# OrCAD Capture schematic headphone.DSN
size A4; title: My Design1; rev: A; company: Parallel Systems Ltd; note: DOC2345798; note: First Floor, Dorna House.; note: 2 Guildford Road, West End
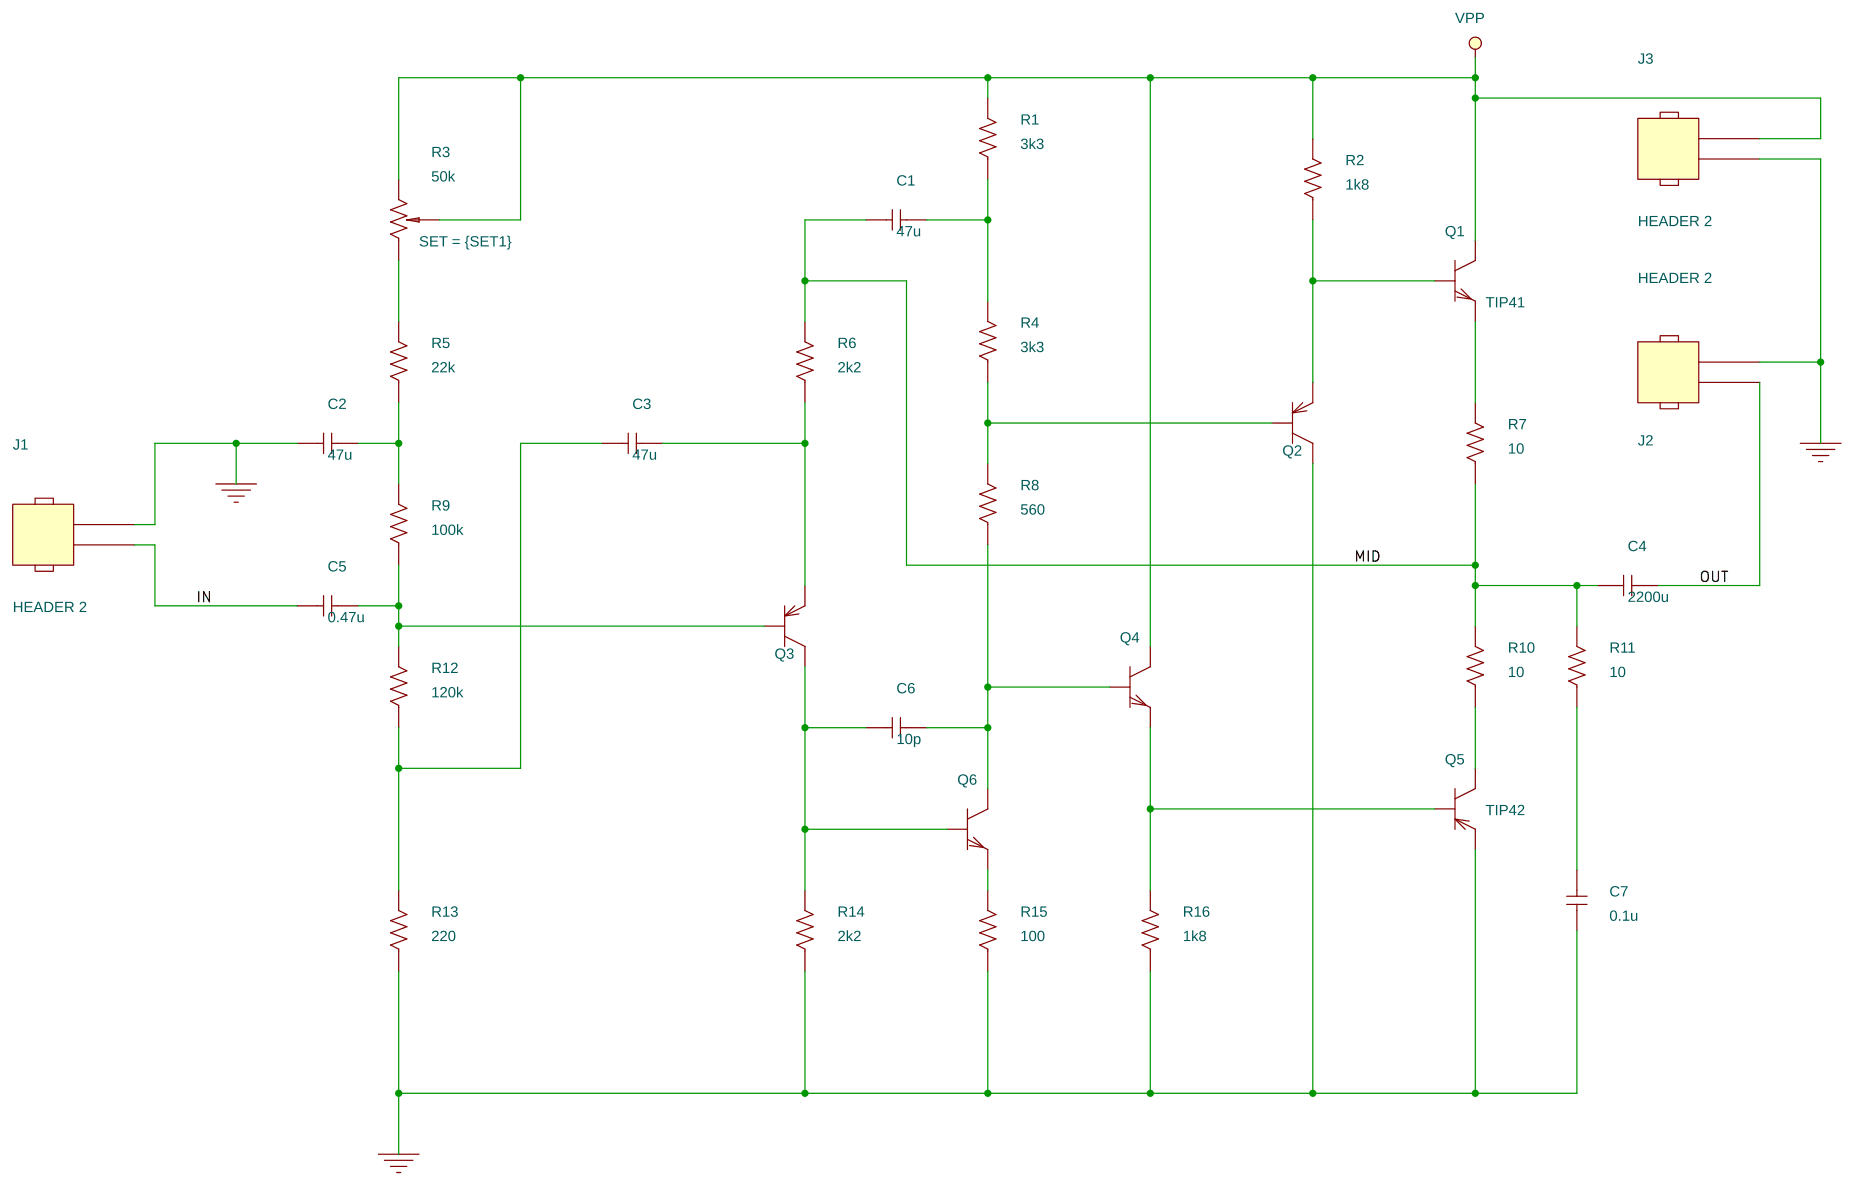
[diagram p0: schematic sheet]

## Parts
C1  47u  [smc0805]
C2  47u  [smc0805]
C3  47u  [smc0805]
C4  2200u  [smc1210]
C5  0.47u  [smc0805]
C6  10p  [smc0805]
C7  0.1u  [smc0805]
J1  HEADER 2  [jumper2]
J2  HEADER 2  [jumper2]
J3  HEADER 2  [jumper2]
Q1  TIP41  [to252aa]
Q2  BC212AP/ZTX  [to236ab]
Q3  BC212AP/ZTX  [to236ab]
Q4  BC182BP/ZTX  [to236ab]
Q5  TIP42  [to252aa]
Q6  BC182BP/ZTX  [to236ab]
R1  3k3  [smr0805]
R2  1k8  [smr0805]
R3  50k  [resadj]
R4  3k3  [smr0805]
R5  22k  [smr0805]
R6  2k2  [smr0805]
R7  10  [smr1206]
R8  560  [smr0805]
R9  100k  [smr0805]
R10  10  [smr0805]
R11  10  [smr0805]
R12  120k  [smr0805]
R13  220  [smr0805]
R14  2k2  [smr0805]
R15  100  [smr0805]
R16  1k8  [smr0805]

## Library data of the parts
C1-C7 = C
J1-J3 = HEADER_2
Q1 = TIP41
Q2 Q3 = BC212AP_ZTX_0
Q4 Q6 = BC182BP_ZTX_0
Q5 = TIP42
R1 R2 R4-R16 = R
R3 = POT: SET: {SET1}

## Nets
0: C2.1 C7.1 J1.1 J2.2 J3.2 Q2.2(c) Q5.3(e) R13.1 R14.1 R15.1 R16.1
IN: C5.1 J1.2
MID: C1.1 C4.1 R6.2 R7.1 R10.2 R11.2
OUT: C4.2 J2.1
VPP: J3.1 Q1.2(c) Q4.2(c) R1.2 R2.2 R3.2(t) R3.3(2)
N1519156: C1.2 R1.1 R4.2
N1519228: Q1.1(b) Q2.3(e) R2.1
N1519232: R3.1 R5.2
N1519306: Q1.3(e) R7.2
N1519352: Q2.1(b) R4.1 R8.2
N1519356: C2.2 R5.1 R9.2
N1519362: C3.2 Q3.3(e) R6.1
N1519474: C3.1 R12.1 R13.2
N1519554: C6.2 Q4.1(b) Q6.2(c) R8.1
N1519560: C5.2 Q3.1(b) R9.1 R12.2
N1519748: C6.1 Q3.2(c) Q6.1(b) R14.2
N1519802: Q5.2(c) R10.1
N1519808: C7.2 R11.1
N1519834: Q4.3(e) Q5.1(b) R16.2
N1519922: Q6.3(e) R15.2
